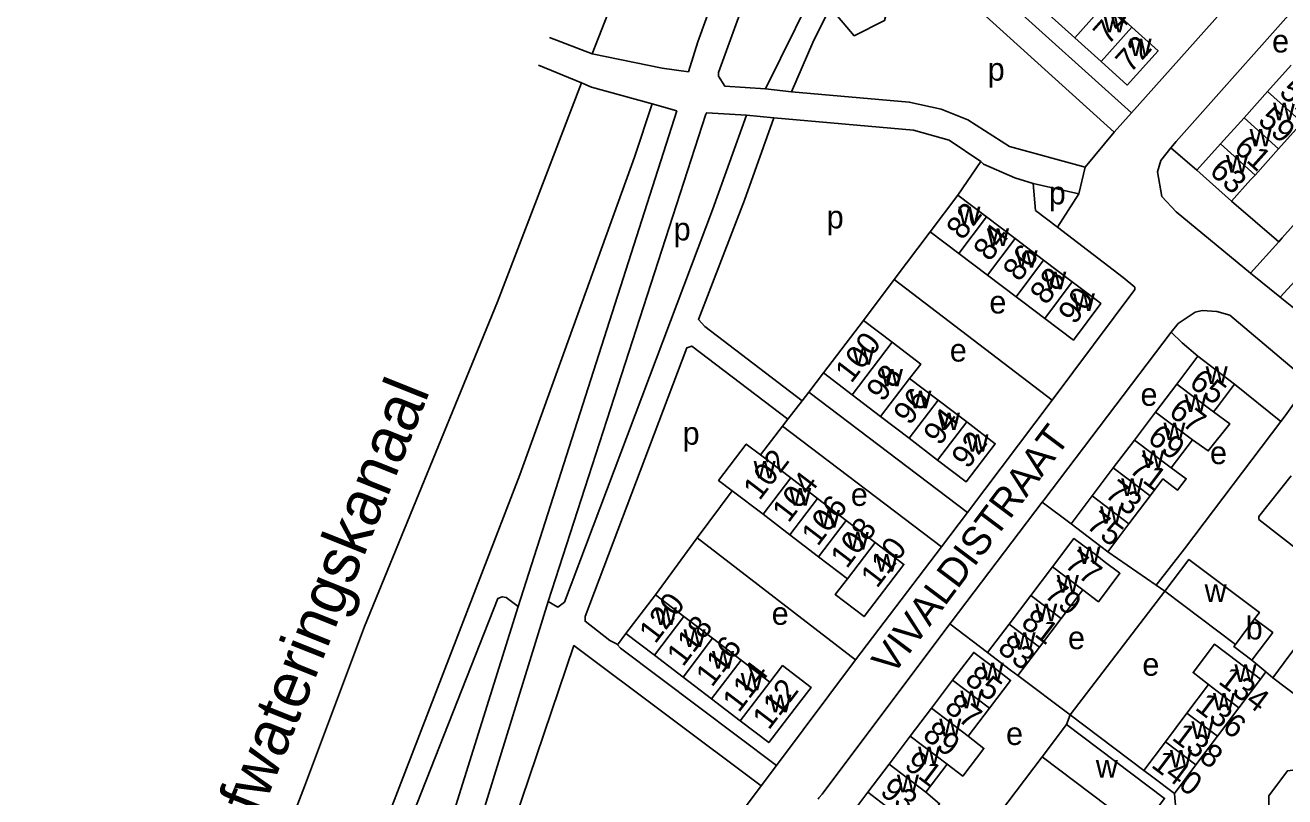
# Model space of a CAD drawing. Extents: x 159045 to 160918, y 380454 to 382516.
# Drawn here: x 159219 to 159439.6, y 381913.4 to 382048.4 of the extents above; entities that cross this region are included whole.
import ezdxf

# ---------------------------------------------------------------- set-up
doc = ezdxf.new("R2010")
doc.units = 0
for name, color, linetype in [('BLT_Basislijn', 7, 'Continuous'), ('BLT_Bebouwing', 7, 'Continuous'), ('BLT_Centroide', 7, 'Continuous'), ('BLT_Huisnummer', 7, 'Continuous'), ('BLT_Huisnummer_ tussenligend', 7, 'Continuous'), ('BLT_Onderverdeling_panden', 7, 'Continuous'), ('BLT_Straatnaam', 7, 'Continuous'), ('BLT_Waternaam_spoorwegen', 7, 'Continuous')]:
    doc.layers.add(name, color=color, linetype=linetype)

msp = doc.modelspace()

# ---------------------------------------------------------------- linework, layer by layer
at = {"layer": 'BLT_Basislijn'}
for p, q in [((159387.02, 382056.3), (159412.8, 382033.08)), ((159322.34, 382053.71), (159318.3, 382043.44)), ((159412.8, 382033.08), (159428.38, 382050.54)), ((159308.89, 382041.43), (159316.41, 382038.34)), ((159348.67, 382037.27), (159353.22, 382036.77)), ((159305.34, 381946.67), (159333.11, 382033.45)), ((159328.78, 382034.66), (159333.11, 382033.45)), ((159409.77, 382029.71), (159412.8, 382033.08)), ((159345.35, 382032.69), (159350.11, 382032.23)), ((159404.65, 382023.61), (159409.77, 382029.71)), ((159419.67, 382026.94), (159424.25, 382023.05)), ((159386.36, 382024.59), (159382.34, 382018.66)), ((159403.57, 382018.89), (159404.65, 382023.61)), ((159403.57, 382018.89), (159395.54, 382020.71)), ((159399.8, 382013.1), (159403.57, 382018.89)), ((159430.31, 382017.61), (159438.58, 382010.52)), ((159371.21, 382003.91), (159377.51, 382012.27)), ((159433.62, 382005.03), (159438.58, 382010.52)), ((159438.83, 382000.81), (159442.73, 382005.06)), ((159365.85, 381996.76), (159371.21, 382003.91)), ((159398.89, 381982.82), (159371.21, 382003.91)), ((159477.49, 381969.9), (159438.83, 382000.81)), ((159356.23, 381984.19), (159358.83, 381987.56)), ((159355.07, 381982.69), (159356.23, 381984.19)), ((159384.03, 381963.12), (159356.23, 381984.19)), ((159438.94, 381979.06), (159430.84, 381985.62)), ((159352.6, 381979.48), (159355.07, 381982.69)), ((159384.03, 381963.12), (159398.89, 381982.82)), ((159347.77, 381973.21), (159351.63, 381978.23)), ((159351.63, 381978.23), (159352.6, 381979.48)), ((159351.63, 381978.23), (159379.5, 381957.12)), ((159342.8, 381966.95), (159336.69, 381958.67)), ((159397.13, 381964.93), (159402.19, 381961.14)), ((159379.5, 381957.12), (159384.03, 381963.12)), ((159336.69, 381958.67), (159329.36, 381948.74)), ((159336.69, 381958.67), (159364.44, 381937.36)), ((159364.44, 381937.36), (159379.5, 381957.12)), ((159417.13, 381950.39), (159408.63, 381956.27)), ((159402.03, 381927.69), (159418.64, 381949.35)), ((159418.64, 381949.35), (159417.13, 381950.39)), ((159387.56, 381938.6), (159380.97, 381943.63)), ((159324.18, 381941.96), (159322.72, 381939.99)), ((159350.6, 381918.82), (159364.44, 381937.36)), ((159436.32, 381935.22), (159433.89, 381937.29)), ((159392.88, 381934.57), (159402.03, 381927.69)), ((159435.38, 381933.96), (159436.32, 381935.22)), ((159437.52, 381934.2), (159436.32, 381935.22)), ((159401.41, 381926), (159402.03, 381927.69)), ((159402.03, 381927.69), (159414.93, 381917.99)), ((159379.14, 381896.71), (159397.14, 381920.33)), ((159347.9, 381915.28), (159350.6, 381918.82)), ((159267.91, 381915.14), (159234.6, 381830.25)), ((159338.92, 381903.34), (159347.9, 381915.28))]:
    msp.add_line(p, q, dxfattribs=at)
for points in [[(159421.69, 382215.85), (159415.79, 382208.81), (159408.92, 382199.96), (159400.59, 382187.82), (159391.83, 382173.72), (159376.55, 382143.99), (159358.26, 382102.74), (159347.5, 382075.04), (159336.81, 382045.51), (159335.16, 382040.3)], [(159348.67, 382037.27), (159341.56, 382037.74), (159340.45, 382039.52), (159340.45, 382040.16), (159354.44, 382078.73), (159370.08, 382116.79), (159381.97, 382143.1), (159397.86, 382174.46), (159415.4, 382200.16), (159421.45, 382207.36), (159423.93, 382207.44)], [(159437.83, 382177.21), (159436.45, 382176.18), (159427.13, 382164.93), (159413.36, 382147.49), (159395.71, 382123.28), (159388.95, 382113.4), (159385.13, 382107.2), (159369.55, 382079.59), (159348.67, 382037.27)], [(159409.77, 382029.71), (159368.44, 382067.04), (159367.87, 382067.22), (159367.16, 382066.23), (159363.9, 382059.57)], [(159363.9, 382059.57), (159373.68, 382056.99), (159372.49, 382052.5), (159370.48, 382053.03), (159369.48, 382049.24), (159364.19, 382046.58), (159359.96, 382051.54)], [(159445.41, 382056.01), (159420.6, 382028.1), (159419.67, 382026.94)], [(159359.96, 382051.54), (159356.94, 382045.38), (159353.22, 382036.77)], [(159318.3, 382043.44), (159310.8, 382046.26)], [(159318.3, 382043.44), (159330.55, 382040.93), (159335.16, 382040.3)], [(159316.41, 382038.34), (159301.7, 382000), (159287.92, 381966.37), (159278.39, 381943.16), (159267.91, 381915.14)], [(159316.41, 382038.34), (159318.2, 382037.61), (159328.78, 382034.66)], [(159438.58, 382010.52), (159439.2, 382011.2), (159458.45, 382032.81), (159464.04, 382039.18)], [(159404.65, 382023.61), (159391.4, 382027.18), (159384.12, 382031.89), (159379.41, 382033.75), (159373.84, 382034.99), (159353.22, 382036.77)], [(159218.96, 381756.51), (159278.75, 381900.16), (159305.63, 381969.71), (159325.69, 382025.34), (159328.78, 382034.66)], [(159345.35, 382032.69), (159338.38, 382033.11), (159338.22, 382032.87), (159310.58, 381947.54)], [(159345.35, 382032.69), (159339.4, 382016.1), (159313.42, 381947.45), (159312.3, 381946.56), (159310.58, 381947.54)], [(159350.11, 382032.23), (159344.96, 382017.83), (159336.9, 381996.92), (159338.01, 381995.71), (159355.07, 381982.69)], [(159350.11, 382032.23), (159374.58, 382030.06), (159380.84, 382028.28), (159386.36, 382024.59)], [(159419.67, 382026.94), (159417.89, 382024.73), (159417.36, 382022.76), (159418.11, 382018.43), (159420.62, 382015.76), (159433.62, 382005.03)], [(159386.36, 382024.59), (159386.88, 382024.09), (159392.34, 382021.7), (159395.54, 382020.71)], [(159399.8, 382013.1), (159395.95, 382016.02), (159395.54, 382020.71)], [(159398.89, 381982.82), (159413.38, 382002.15), (159413.38, 382002.56), (159411.32, 382004.24), (159399.8, 382013.1)], [(159433.62, 382005.03), (159438.75, 382000.88), (159438.83, 382000.81)], [(159419.74, 381994.69), (159420.98, 381996.2), (159423.95, 381998.17), (159425.15, 381998.47), (159427.71, 381998.3), (159429.98, 381997.7), (159443.91, 381985.92)], [(159419.74, 381994.69), (159397.4, 381965.29), (159397.13, 381964.93)], [(159419.74, 381994.69), (159421.67, 381992.81), (159424.4, 381990.49)], [(159322.72, 381939.99), (159322.57, 381940.16), (159321.39, 381940.74), (159317.04, 381944.08), (159317.04, 381944.94), (159334.88, 381991.97), (159335.74, 381992.25), (159352.6, 381979.48)], [(159443.91, 381985.92), (159439.69, 381980.04), (159438.94, 381979.06)], [(159417.13, 381950.39), (159422.04, 381956.76), (159438.94, 381979.06)], [(159440.76, 381969.52), (159435.06, 381962.4), (159435.06, 381961.92), (159449.92, 381950.36)], [(159380.97, 381943.63), (159381.18, 381943.91), (159397.13, 381964.93)], [(159228.53, 381768.8), (159280.55, 381894.35), (159301.76, 381948.05), (159302.55, 381948.37), (159303.24, 381948.24), (159305.34, 381946.67)], [(159239.72, 381764.18), (159261.82, 381819.83), (159277.26, 381860.99), (159289.55, 381896.38), (159305.34, 381946.67)], [(159284.45, 381868.28), (159295.77, 381899.59), (159310.58, 381947.54)], [(159380.97, 381943.63), (159358.58, 381913.8), (159357.99, 381913.2), (159357.91, 381912.95)], [(159306.91, 381864.2), (159306.4, 381864.24), (159305.05, 381864.34), (159292.82, 381871.98), (159292.81, 381872.77), (159300.7, 381897.45), (159315.1, 381939.82), (159347.9, 381915.28)], [(159350.6, 381918.82), (159323.24, 381939.38), (159322.72, 381939.99)], [(159442.89, 381906.63), (159437.96, 381910.51), (159436.85, 381911.92), (159436.82, 381913.53), (159440.1, 381917.9), (159442.42, 381918.17), (159448.73, 381913.49)], [(159420.49, 381911.89), (159420.36, 381913.2), (159420.29, 381913.95)]]:
    msp.add_lwpolyline(points, dxfattribs=at)
at = {"layer": 'BLT_Bebouwing'}
for p, q in [((159408.24, 382052.21), (159412.84, 382048.08)), ((159402.86, 382046.21), (159398.27, 382050.33)), ((159407.46, 382042.09), (159402.86, 382046.21)), ((159440.73, 382041.42), (159436.61, 382036.83)), ((159436.61, 382036.83), (159432.49, 382032.24)), ((159432.49, 382032.24), (159428.37, 382027.64)), ((159438.55, 382026.8), (159442.67, 382031.39)), ((159428.37, 382027.64), (159424.25, 382023.05)), ((159434.43, 382022.21), (159438.55, 382026.8)), ((159424.25, 382023.05), (159430.31, 382017.61)), ((159377.51, 382012.27), (159382.34, 382018.66)), ((159382.34, 382018.66), (159387.36, 382014.87)), ((159387.36, 382014.87), (159392.37, 382011.08)), ((159382.53, 382008.48), (159377.51, 382012.27)), ((159392.37, 382011.08), (159397.39, 382007.29)), ((159387.54, 382004.69), (159382.53, 382008.48)), ((159397.39, 382007.29), (159402.41, 382003.5)), ((159392.56, 382000.89), (159387.54, 382004.69)), ((159358.83, 381987.56), (159365.85, 381996.76)), ((159424.4, 381990.49), (159420.7, 381985.6)), ((159430.84, 381985.62), (159424.4, 381990.49)), ((159363.83, 381983.75), (159358.83, 381987.56)), ((159373.91, 381986.61), (159378.91, 381982.8)), ((159420.7, 381985.6), (159417, 381980.71)), ((159368.82, 381979.94), (159363.83, 381983.75)), ((159378.91, 381982.8), (159383.91, 381978.99)), ((159373.82, 381976.13), (159368.82, 381979.94)), ((159417, 381980.71), (159413.3, 381975.82)), ((159378.82, 381972.31), (159373.82, 381976.13)), ((159413.3, 381975.82), (159409.59, 381970.93)), ((159423.44, 381975.84), (159419.74, 381970.94)), ((159347.77, 381973.21), (159353.07, 381969.17)), ((159353.07, 381969.17), (159357.75, 381965.6)), ((159409.59, 381970.93), (159405.89, 381966.04)), ((159357.75, 381965.6), (159362.8, 381961.75)), ((159405.89, 381966.04), (159402.19, 381961.14)), ((159416.03, 381966.05), (159412.33, 381961.16)), ((159352.9, 381959.24), (159348.23, 381962.81)), ((159362.8, 381961.75), (159367.85, 381957.89)), ((159412.33, 381961.16), (159408.63, 381956.27)), ((159357.95, 381955.39), (159352.9, 381959.24)), ((159363, 381951.54), (159357.95, 381955.39)), ((159398.92, 381953.6), (159395.13, 381948.6)), ((159404.24, 381949.57), (159400.46, 381944.57)), ((159418.64, 381949.35), (159431.01, 381940.04)), ((159324.18, 381941.96), (159329.36, 381948.74)), ((159329.36, 381948.74), (159334.37, 381944.92)), ((159395.13, 381948.6), (159391.35, 381943.6)), ((159334.37, 381944.92), (159339.39, 381941.1)), ((159400.46, 381944.57), (159396.67, 381939.57)), ((159391.35, 381943.6), (159387.56, 381938.6)), ((159329.19, 381938.13), (159324.18, 381941.96)), ((159339.39, 381941.1), (159344.4, 381937.27)), ((159334.21, 381934.31), (159329.19, 381938.13)), ((159396.67, 381939.57), (159392.88, 381934.57)), ((159344.4, 381937.27), (159349.41, 381933.45)), ((159339.22, 381930.48), (159334.21, 381934.31)), ((159377.72, 381928.85), (159381.43, 381933.75)), ((159431.61, 381928.96), (159435.38, 381933.96)), ((159437.52, 381934.2), (159442.59, 381930.42)), ((159426.26, 381933), (159422.48, 381927.99)), ((159344.23, 381926.66), (159339.22, 381930.48)), ((159374.01, 381923.95), (159377.72, 381928.85)), ((159384.19, 381923.95), (159387.9, 381928.85)), ((159422.48, 381927.99), (159418.71, 381922.99)), ((159427.84, 381923.96), (159431.61, 381928.96)), ((159370.3, 381919.05), (159374.01, 381923.95)), ((159418.71, 381922.99), (159414.93, 381917.99)), ((159424.06, 381918.95), (159427.84, 381923.96)), ((159366.59, 381914.15), (159370.3, 381919.05)), ((159376.77, 381914.15), (159380.48, 381919.05)), ((159420.29, 381913.95), (159424.06, 381918.95)), ((159362.88, 381909.25), (159366.59, 381914.15))]:
    msp.add_line(p, q, dxfattribs=at)
for points in [[(159412.84, 382048.08), (159417.43, 382043.96), (159412.05, 382037.96), (159407.46, 382042.09)], [(159430.31, 382017.61), (159433.65, 382021.34), (159434.43, 382022.21)], [(159397.58, 381997.11), (159402.6, 381993.32), (159407.43, 381999.71), (159407.04, 382000), (159402.41, 382003.5)], [(159397.58, 381997.11), (159393.75, 382000), (159392.56, 382000.89)], [(159365.85, 381996.76), (159370.85, 381992.95)], [(159370.85, 381992.95), (159375.86, 381989.12), (159374.98, 381987.97), (159373.91, 381986.61)], [(159430.84, 381985.62), (159427.83, 381981.63), (159427.14, 381980.73)], [(159427.14, 381980.73), (159430, 381978.66), (159426.24, 381973.92), (159423.44, 381975.84)], [(159383.91, 381978.99), (159388.91, 381975.17), (159383.82, 381968.5), (159378.82, 381972.31)], [(159342.8, 381966.95), (159340.43, 381968.75), (159345.28, 381975.11), (159347.77, 381973.21)], [(159419.74, 381970.94), (159422.37, 381969.04), (159420.85, 381967.04), (159418.27, 381969), (159416.03, 381966.05)], [(159348.23, 381962.81), (159342.8, 381966.95)], [(159402.19, 381961.14), (159406.17, 381958.13), (159408.63, 381956.27)], [(159367.85, 381957.89), (159372.9, 381954.04), (159365.93, 381944.91), (159360.89, 381948.76), (159363, 381951.54)], [(159404.24, 381949.57), (159406.97, 381947.49), (159410.76, 381952.49), (159408.02, 381954.57), (159406.69, 381955.58), (159402.7, 381958.6), (159398.92, 381953.6)], [(159434.35, 381944.52), (159435.18, 381945.63), (159422.83, 381954.92), (159418.64, 381949.35)], [(159433.89, 381937.29), (159437.53, 381942.12), (159434.35, 381944.52)], [(159435.38, 381933.96), (159431.39, 381936.98), (159427.31, 381940.05), (159423.58, 381935.11), (159426.26, 381933)], [(159442.39, 381940.67), (159440.51, 381938.21), (159437.52, 381934.2)], [(159381.43, 381933.75), (159385.13, 381938.64), (159389.12, 381935.62), (159391.6, 381933.74), (159387.9, 381928.85)], [(159387.56, 381938.6), (159391.59, 381935.55), (159392.88, 381934.57)], [(159431.01, 381940.04), (159430.73, 381939.67), (159433.89, 381937.29)], [(159349.41, 381933.45), (159351.64, 381936.33), (159356.64, 381932.52), (159354.42, 381929.62), (159349.24, 381922.84), (159344.23, 381926.66)], [(159401.41, 381926), (159418.58, 381913.09), (159414.31, 381907.41), (159397.14, 381920.33)], [(159397.14, 381920.33), (159401.41, 381926)], [(159380.48, 381919.05), (159383.23, 381916.98), (159386.91, 381921.84), (159384.19, 381923.95)], [(159414.93, 381917.99), (159416.3, 381916.96), (159420.29, 381913.95)], [(159375.51, 381907.34), (159379.15, 381912.15), (159376.77, 381914.15)]]:
    msp.add_lwpolyline(points, dxfattribs=at)
at = {"layer": 'BLT_Onderverdeling_panden'}
for p, q in [((159402.86, 382046.21), (159408.24, 382052.21)), ((159407.46, 382042.09), (159412.84, 382048.08)), ((159442.67, 382031.39), (159436.61, 382036.83)), ((159438.55, 382026.8), (159432.49, 382032.24)), ((159434.43, 382022.21), (159428.37, 382027.64)), ((159382.53, 382008.48), (159387.36, 382014.87)), ((159387.54, 382004.69), (159392.37, 382011.08)), ((159392.56, 382000.89), (159397.39, 382007.29)), ((159397.58, 381997.11), (159402.41, 382003.5)), ((159363.83, 381983.75), (159370.85, 381992.95)), ((159368.82, 381979.94), (159373.91, 381986.61)), ((159427.14, 381980.73), (159420.7, 381985.6)), ((159373.82, 381976.13), (159378.91, 381982.8)), ((159423.44, 381975.84), (159417, 381980.71)), ((159378.82, 381972.31), (159383.91, 381978.99)), ((159419.74, 381970.94), (159413.3, 381975.82)), ((159348.23, 381962.81), (159353.07, 381969.17)), ((159416.03, 381966.05), (159409.59, 381970.93)), ((159352.9, 381959.24), (159357.75, 381965.6)), ((159412.33, 381961.16), (159405.89, 381966.04)), ((159357.95, 381955.39), (159362.8, 381961.75)), ((159363, 381951.54), (159367.85, 381957.89)), ((159404.24, 381949.57), (159398.92, 381953.6)), ((159400.46, 381944.57), (159395.13, 381948.6)), ((159329.19, 381938.13), (159334.37, 381944.92)), ((159434.35, 381944.52), (159431.01, 381940.04)), ((159396.67, 381939.57), (159391.35, 381943.6)), ((159334.21, 381934.31), (159339.39, 381941.1)), ((159339.22, 381930.48), (159344.4, 381937.27)), ((159344.23, 381926.66), (159349.41, 381933.45)), ((159387.9, 381928.85), (159381.43, 381933.75)), ((159431.61, 381928.96), (159426.26, 381933)), ((159384.19, 381923.95), (159377.72, 381928.85)), ((159427.84, 381923.96), (159422.48, 381927.99)), ((159380.48, 381919.05), (159374.01, 381923.95)), ((159424.06, 381918.95), (159418.71, 381922.99)), ((159376.77, 381914.15), (159370.3, 381919.05)), ((159375.51, 381907.34), (159366.59, 381914.15))]:
    msp.add_line(p, q, dxfattribs=at)

# ---------------------------------------------------------------- texts
at = {"layer": 'BLT_Centroide'}
for s, p in [('w', (159407.84, 382047.16)), ('w', (159412.45, 382043.03)), ('e', (159437.41, 382043.66)), ('p', (159387.59, 382038.73)), ('w', (159437.59, 382031.81)), ('w', (159433.46, 382027.22)), ('w', (159429.34, 382022.62)), ('p', (159398.29, 382017.08)), ('p', (159359.38, 382012.87)), ('w', (159382.44, 382013.58)), ('p', (159332.57, 382010.77)), ('w', (159387.45, 382009.78)), ('w', (159392.47, 382005.98)), ('w', (159397.48, 382002.2)), ('e', (159387.88, 381997.97)), ('w', (159402.5, 381998.42)), ('w', (159363.88, 381989)), ('e', (159380.95, 381989.55)), ('w', (159425.77, 381985.62)), ('w', (159368.88, 381985.19)), ('w', (159373.86, 381981.38)), ('e', (159414.36, 381981.8)), ('w', (159422.07, 381980.72)), ('w', (159378.86, 381977.56)), ('p', (159334.14, 381975)), ('w', (159418.37, 381975.81)), ('w', (159383.86, 381973.75)), ('w', (159414.66, 381970.94)), ('e', (159426.53, 381971.6)), ('w', (159346.57, 381969.09)), ('w', (159410.96, 381966.03)), ('w', (159352.8, 381964.34)), ('e', (159363.61, 381964.28)), ('w', (159357.84, 381960.5)), ('w', (159407.26, 381961.16)), ('w', (159362.89, 381956.64)), ('w', (159367.95, 381952.78)), ('w', (159403.47, 381954.09)), ('w', (159399.69, 381949.09)), ('w', (159425.59, 381947.47)), ('w', (159395.91, 381944.09)), ('w', (159329.28, 381943.44)), ('e', (159349.74, 381943.46)), ('b', (159432.79, 381940.91)), ('w', (159334.3, 381939.61)), ('e', (159401.65, 381939.2)), ('w', (159392.12, 381939.09)), ('w', (159339.3, 381935.8)), ('w', (159386.52, 381933.75)), ('e', (159414.68, 381934.55)), ('w', (159430.82, 381933.47)), ('w', (159344.31, 381931.97)), ('w', (159382.8, 381928.84)), ('w', (159427.05, 381928.47)), ('w', (159349.33, 381928.14)), ('w', (159379.1, 381923.94)), ('e', (159390.8, 381922.43)), ('w', (159423.27, 381923.47)), ('w', (159375.39, 381919.06)), ('w', (159419.5, 381918.47)), ('w', (159406.53, 381916.72)), ('w', (159371.68, 381914.16))]:
    msp.add_text(s, height=4, dxfattribs=at).set_placement(p)
at = {"layer": 'BLT_Huisnummer'}
for s, rotation, p in [('72', 48.0947, (159412.6, 382039.91)), ('57', 318.0923, (159438.46, 382036.43)), ('63', 318.0923, (159426.23, 382022.61)), ('82', 52.9442, (159383.2, 382010.64)), ('86', 52.9441, (159393.11, 382003.36)), ('90', 52.9455, (159402.81, 381995.86)), ('100', 52.6549, (159363.69, 381985.6)), ('65', 322.8718, (159422.67, 381985.39)), ('96', 52.6575, (159373.93, 381978.24)), ('69', 322.8761, (159415.36, 381975.7)), ('92', 52.6604, (159384.11, 381970.61)), ('102', 52.6613, (159347.61, 381965.08)), ('73', 322.8663, (159407.89, 381966.02)), ('106', 52.6626, (159357.81, 381957.06)), ('110', 52.6569, (159368.19, 381949.72)), ('77', 322.8743, (159400.84, 381953.72)), ('120', 52.663, (159329.34, 381940)), ('81', 322.8743, (159393.21, 381943.41)), ('116', 52.6589, (159339.28, 381932.41)), ('85', 322.8716, (159383.38, 381933.49)), ('134', 322.9763, (159427.81, 381933.31)), ('112', 52.6617, (159349.24, 381924.91)), ('89', 322.8758, (159375.98, 381923.76)), ('140', 322.9674, (159416.05, 381918.68))]:
    msp.add_text(s, height=4, rotation=rotation, dxfattribs=at).set_placement(p)
at = {"layer": 'BLT_Huisnummer_ tussenligend'}
for s, rotation, p in [('74', 48.0947, (159408.68, 382044.82)), ('59', 318.0923, (159434.74, 382031.5)), ('61', 318.0923, (159430.5, 382026.61)), ('84', 52.9442, (159387.94, 382006.9)), ('88', 52.9441, (159397.86, 381999.29)), ('98', 52.6575, (159369.19, 381982.32)), ('67', 322.8718, (159419.09, 381980.3)), ('94', 52.6604, (159379.18, 381974.67)), ('71', 322.8761, (159412.16, 381970.34)), ('104', 52.6613, (159352.69, 381961.17)), ('108', 52.6626, (159362.9, 381953.16)), ('75', 322.8663, (159404.66, 381960.58)), ('79', 322.8743, (159397.28, 381948.45)), ('118', 52.6589, (159334.2, 381935.98)), ('83', 322.8743, (159389.12, 381938.93)), ('114', 52.6617, (159343.98, 381927.95)), ('87', 322.8716, (159379.81, 381928.58)), ('136', 322.9763, (159423.74, 381928.73)), ('138', 322.9763, (159419.68, 381923.46)), ('91', 322.8758, (159372.79, 381918.56)), ('93', 322.8758, (159368.53, 381913.91))]:
    msp.add_text(s, height=4, rotation=rotation, dxfattribs=at).set_placement(p)
at = {"layer": 'BLT_Straatnaam'}
msp.add_text('VIVALDISTRAAT', height=5, rotation=53.1184, dxfattribs=at).set_placement((159370.92, 381934.41))
at = {"layer": 'BLT_Waternaam_spoorwegen'}
msp.add_text('Afwateringskanaal', height=8, rotation=68.2296, dxfattribs=at).set_placement((159257.51, 381903.27))

doc.saveas('drawing.dxf')
